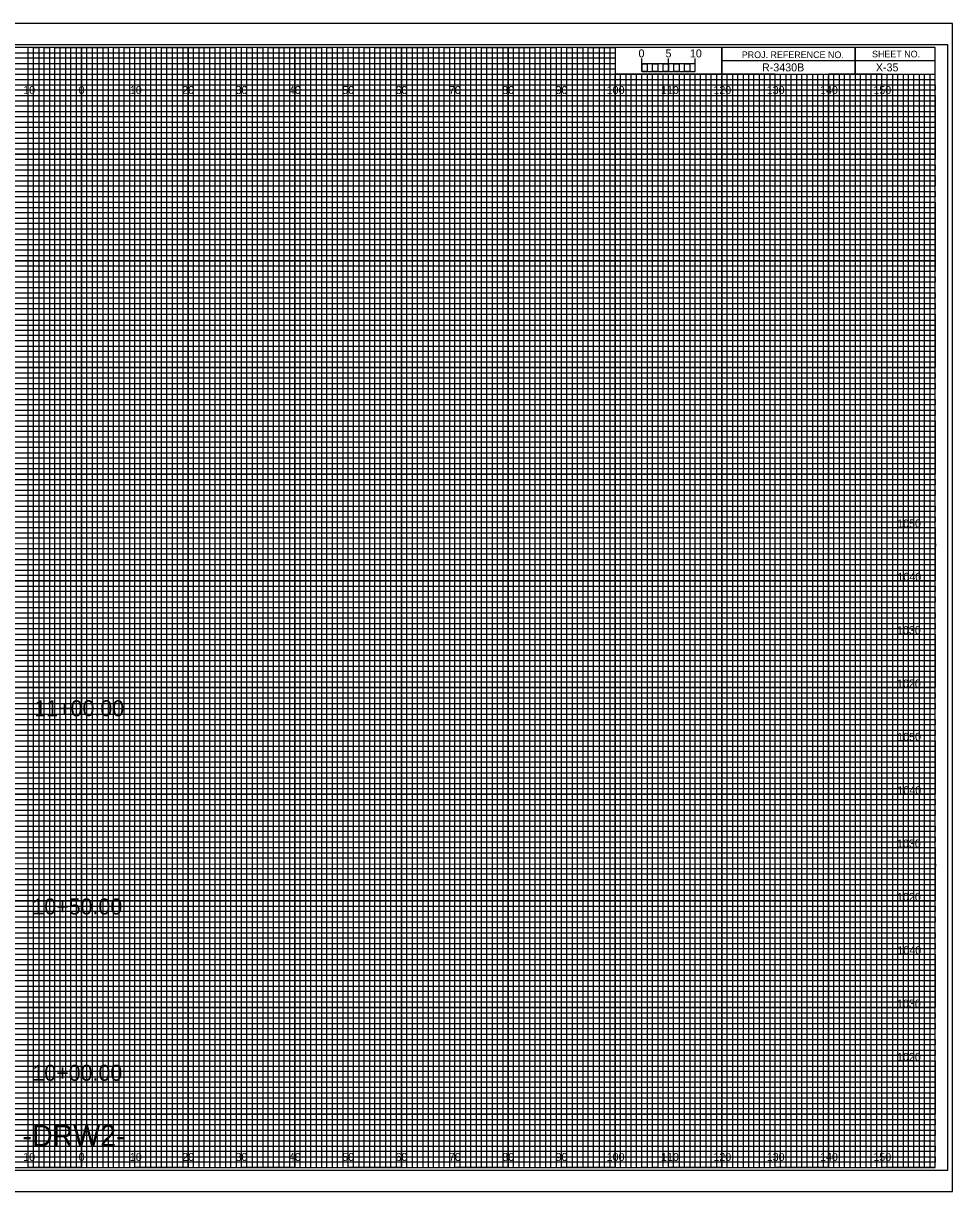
# Model space of a CAD drawing. Extents: x -13 to 323, y -5 to 215.
# Drawn here: x 149.1 to 323.3, y -4.5 to 214.5 of the extents above; entities that cross this region are included whole.
import ezdxf

# ---------------------------------------------------------------- set-up
doc = ezdxf.new("R2010")
doc.units = 0
for name, color, linetype in [('Prop XS Alignment Label', 7, 'Continuous'), ('Prop XS Bar Scale Labels', 7, 'Continuous'), ('Prop XS Elevation Labels', 7, 'Continuous'), ('Prop XS Offset Labels', 7, 'Continuous'), ('Prop XS Project Number', 7, 'Continuous'), ('Prop XS Sheet Number', 7, 'Continuous'), ('Prop XS Station Labels', 7, 'Continuous'), ('Sheet Cross Section CELL', 7, 'Continuous'), ('Sheet Cross Section Grid Major CELL', 7, 'Continuous'), ('Sheet Cross Section Grid Middle CELL', 7, 'Continuous'), ('Sheet Cross Section Grid Minor 1 CELL', 7, 'Continuous'), ('Sheet Cross Section Grid Minor 2 CELL', 7, 'Continuous'), ('Sheet Cross Section Scale CELL', 7, 'Continuous'), ('Sheet Cutting Line CELL', 7, 'Continuous'), ('Sheet DOT Grid CELL', 7, 'Continuous'), ('Sheet Plot Border Inside CELL', 7, 'Continuous'), ('Sheet Plot Border Outside CELL', 7, 'Continuous')]:
    doc.layers.add(name, color=color, linetype=linetype)

msp = doc.modelspace()

# ---------------------------------------------------------------- linework, layer by layer
at = {"layer": 'Sheet Cross Section CELL'}
for p, q in [((305, 210), (305, 205)), ((305, 205), (305, 210)), ((280, 207.5), (280, 205)), ((320, 207.49), (280, 207.49)), ((280, 205), (320, 205))]:
    msp.add_line(p, q, dxfattribs=at)
for points in [[(320, 210), (0, 210), (0, 0), (320, 0)], [(280, 210), (260, 210), (260, 205.03), (280, 205.03)], [(320, 210), (280, 210), (280, 205), (320, 205)]]:
    msp.add_lwpolyline(points, close=True, dxfattribs=at)
at = {"layer": 'Sheet Cross Section Grid Major CELL'}
for p, q in [((150, 210), (140, 210)), ((150, 0), (150, 210)), ((170, 210), (160, 210)), ((160, 210), (160, 0)), ((170, 0), (170, 210)), ((190, 210), (180, 210)), ((180, 210), (180, 0)), ((190, 0), (190, 210)), ((210, 210), (200, 210)), ((200, 210), (200, 0)), ((210, 0), (210, 210)), ((230, 210), (220, 210)), ((220, 210), (220, 0)), ((230, 0), (230, 210)), ((250, 210), (240, 210)), ((240, 210), (240, 0)), ((250, 0), (250, 210)), ((260, 210), (260, 0)), ((270, 0), (270, 205)), ((290, 205), (280, 205)), ((280, 205), (280, 0)), ((290, 0), (290, 205)), ((310, 205), (300, 205)), ((300, 205), (300, 0)), ((310, 0), (310, 205)), ((160, 0), (150, 0)), ((180, 0), (170, 0)), ((200, 0), (190, 0)), ((220, 0), (210, 0)), ((240, 0), (230, 0)), ((260, 0), (250, 0)), ((280, 0), (270, 0)), ((300, 0), (290, 0)), ((320, 0), (310, 0)), ((320, 0), (320, 0))]:
    msp.add_line(p, q, dxfattribs=at)
for points in [[(0, 200), (320, 200), (320, 190), (0, 190)], [(0, 180), (320, 180), (320, 170), (0, 170)], [(0, 160), (320, 160), (320, 150), (0, 150)], [(0, 140), (320, 140), (320, 130), (0, 130)], [(0, 120), (320, 120), (320, 110), (0, 110)], [(0, 100), (320, 100), (320, 90), (0, 90)], [(0, 80), (320, 80), (320, 70), (0, 70)], [(0, 60), (320, 60), (320, 50), (0, 50)], [(0, 40), (320, 40), (320, 30), (0, 30)], [(0, 20), (320, 20), (320, 10), (0, 10)]]:
    msp.add_lwpolyline(points, dxfattribs=at)
at = {"layer": 'Sheet Cross Section Grid Middle CELL'}
for points in [[(145, 0), (155, 0), (155, 210), (165, 210), (165, 0), (175, 0), (175, 210), (185, 210), (185, 0), (195, 0), (195, 210), (205, 210), (205, 0), (215, 0), (215, 210), (225, 210), (225, 0), (235, 0), (235, 210), (245, 210), (245, 0), (255, 0), (255, 210), (259.93, 210), (260, 210), (260, 205), (264.99, 205), (264.99, 0), (275, 0), (275, 205), (285, 205), (285, 0), (295, 0), (295, 205), (305, 205), (305, 0), (315, 0), (315, 205)], [(0, 205), (275, 205)], [(0, 185), (320, 185), (320, 195), (0, 195)], [(0, 165), (320, 165), (320, 175), (0, 175)], [(0, 145), (320, 145), (320, 155), (0, 155)], [(0, 125), (320, 125), (320, 135), (0, 135)], [(0, 105), (320, 105), (320, 115), (0, 115)], [(0, 85), (320, 85), (320, 95), (0, 95)], [(0, 65), (320, 65), (320, 75), (0, 75)], [(0, 45), (320, 45), (320, 55), (0, 55)], [(0, 25), (320, 25), (320, 35), (0, 35)], [(0, 5), (320, 5), (320, 15), (0, 15)]]:
    msp.add_lwpolyline(points, dxfattribs=at)
at = {"layer": 'Sheet Cross Section Grid Minor 1 CELL'}
for p, q in [((0, 209), (260, 209)), ((260, 209), (260, 207.98)), ((260, 207.98), (0, 207.98)), ((0, 207), (260, 207)), ((260, 205.89), (0, 205.89)), ((260, 207), (260, 205.89)), ((0, 204), (320, 204))]:
    msp.add_line(p, q, dxfattribs=at)
for points in [[(0, 203), (270, 203), (320, 203), (320, 202), (0, 202)], [(0, 201), (320, 201), (320, 199), (0, 199)], [(0, 198), (320, 198), (320, 197), (0, 196.98)], [(0, 196), (320, 196), (320, 194), (0, 194)], [(0, 193), (320, 193), (320, 192), (0, 192)], [(0, 191), (320, 191), (320, 189), (0, 189)], [(0, 188), (320, 188), (320, 187), (0, 187)], [(0, 186), (320, 186), (320, 184), (0, 184)], [(0, 183), (320, 183), (320, 182), (0, 182)], [(0, 181), (320, 181), (320, 179), (0, 179)], [(0, 178), (320, 178), (320, 177), (0, 177)], [(0, 176), (320, 176), (320, 173.95), (320, 173), (320, 172), (0, 172)], [(0, 174), (320, 174), (320, 173), (0, 173)], [(0, 171), (320, 171), (320, 169), (0, 169.03)], [(0, 169.03), (320, 169), (320, 168), (0, 168)], [(0, 167), (320, 167), (320, 166), (0, 166)], [(0, 164), (320, 164), (320, 163), (0, 163)], [(0, 162), (320, 162), (320, 161), (0, 161)], [(-0.07, 158.89), (320, 158.89), (320, 157.88), (-0.07, 157.88)], [(0, 157), (320, 157), (320, 156), (0, 156)], [(0, 154), (320, 154), (320, 153), (0, 153)], [(0, 152), (320, 152), (320, 151), (0, 151)], [(0, 149), (320, 149), (320, 148), (0, 148)], [(0, 147), (320, 147), (320, 146), (0, 146)], [(0, 144), (320, 144), (320, 143), (0, 143)], [(0, 142), (320, 142), (320, 141), (0, 141)], [(0, 139), (320, 139), (319.99, 137.98), (0, 138)], [(0, 137), (320, 137), (320, 136), (0, 136)], [(0, 134), (320, 134), (320, 133), (0, 133)], [(0, 132), (320, 132), (320, 131), (0, 131)], [(0, 129), (320, 129), (320, 128), (0, 128)], [(0, 127), (320, 127), (320, 126), (0, 126)], [(0, 124), (320, 124), (320, 123), (0, 123)], [(0, 122), (320, 122), (320, 121), (0, 121)], [(0, 119), (320, 119), (320, 118), (0, 118)], [(0, 116.99), (320.07, 116.91), (320, 116), (0, 116)], [(0, 114), (320, 114), (320, 113), (0, 113)], [(0, 112), (320, 112), (320, 111), (0, 111)], [(0, 109), (320, 109), (320, 108), (0, 108)], [(0, 107), (320, 107), (320, 106), (0, 106)], [(0, 104), (320, 104), (320, 103), (0, 103)], [(0, 102), (320, 102), (320, 101), (0, 101)], [(0, 99), (320, 99), (320, 98), (0, 98)], [(0, 97), (320, 97), (320, 96), (0, 96)], [(0, 94), (320, 94), (320, 93), (0, 93)], [(0, 92), (320, 92), (320, 91), (0, 91)], [(0, 89), (320, 89), (320, 88), (0, 88)], [(0, 87), (320, 87), (320, 86), (0, 86)], [(0, 84), (320, 84), (320, 83), (0, 83)], [(0, 82), (320, 82), (320, 81), (0, 81)], [(0, 79), (320, 79), (319.99, 77.98), (0, 78)], [(0, 77), (320, 77), (320, 76), (0, 76)], [(0, 74), (320, 74), (320, 73), (0, 73)], [(0, 72), (320, 72), (320, 71), (0, 71)], [(0, 69), (320, 69), (320, 68), (0, 68)], [(0, 67), (320, 67), (320, 66), (0, 66)], [(0, 64), (320, 64), (320, 63), (0, 63)], [(0, 62), (320, 62), (320, 61), (0, 61)], [(0, 59), (320, 59), (320, 58), (0, 58)], [(0, 56.99), (320.07, 56.91), (320, 56), (0, 56)], [(0, 54), (320, 54), (320, 53), (0, 53)], [(0, 52), (320, 52), (320, 51), (0, 51)], [(0, 49), (320, 49), (320, 48), (0, 48)], [(0, 47), (320, 47), (320, 46), (0, 46)], [(0, 44), (320, 44), (320, 43), (0, 43)], [(0, 42), (320, 42), (320, 41), (0, 41)], [(0, 39), (320, 39), (320, 38), (0, 38)], [(0, 37), (320, 37), (320, 36), (0, 36)], [(0, 34), (320, 34), (320, 33), (0, 33)], [(0, 32), (320, 32), (320, 31), (0, 31)], [(0, 29), (320, 29), (320, 28), (0, 28)], [(0, 27), (320, 27), (320, 26), (0, 26)], [(0, 24), (320, 24), (320, 23), (0, 23)], [(0, 22), (320, 22), (320, 21), (0, 21)], [(0, 19), (320, 19), (320, 18), (0, 18)], [(0, 17), (320, 17), (320, 16), (0, 16)], [(0, 14), (320, 14), (320, 13), (0, 13)], [(0, 12), (320, 12), (320, 11), (0, 11)], [(0, 9), (320, 9), (320, 8), (0, 8)], [(0, 7), (320, 7), (320, 6), (0, 6)], [(0, 4), (320, 4), (320, 3), (0, 3)], [(0, 2), (320, 2), (320, 1), (0, 1)]]:
    msp.add_lwpolyline(points, dxfattribs=at)
at = {"layer": 'Sheet Cross Section Grid Minor 2 CELL'}
for p, q in [((267, 205), (266.01, 205)), ((266.01, 205), (266.01, 0)), ((267, 0), (267, 205)), ((269, 205), (268, 205)), ((268, 205), (268, 0)), ((269, 0), (269, 205)), ((266.01, 0), (265, 0)), ((268, 0), (267, 0))]:
    msp.add_line(p, q, dxfattribs=at)
for points in [[(150, 0), (151, 0), (151, 210), (152, 210), (152, 0)], [(152, 0), (153, 0), (153, 210), (154, 210), (154, 0)], [(155, 0), (156, 0), (156, 210), (157, 210), (157, 0)], [(157, 0), (158, 0), (158, 210), (159, 210), (159, 0)], [(160, 0), (161, 0), (161, 210), (162, 210), (162, 0)], [(162, 0), (163, 0), (163, 210), (164, 210), (164, 0)], [(165, 0), (166, 0), (166, 210), (167, 210), (167, 0)], [(167, 0), (168, 0), (168, 210), (169, 210), (169, 0)], [(170, 0), (171, 0), (171, 210), (172, 210), (172, 0)], [(172, 0), (173, 0), (173, 210), (174, 210), (174, 0)], [(175, 0), (176, 0), (176, 210), (177, 210), (177, 0)], [(177, 0), (178, 0), (178, 210), (179, 210), (179, 0)], [(180, 0), (181, 0), (181, 210), (182, 210), (182, 0)], [(182, 0), (183, 0), (183, 210), (184, 210), (184, 0)], [(185, 0), (186, 0), (186, 210), (187, 210), (187, 0)], [(187, 0), (188, 0), (188, 210), (189, 210), (189, 0)], [(190, 0), (191, 0), (191, 210), (192, 210), (192, 0)], [(192, 0), (193, 0), (193, 210), (194, 210), (194, 0)], [(195, 0), (196, 0), (196, 210), (197, 210), (197, 0)], [(197, 0), (198, 0), (198, 210), (199, 210), (199, 0)], [(200, 0), (201, 0), (201, 210), (202, 210), (202, 0)], [(202, 0), (203, 0), (203, 210), (204, 210), (204, 0)], [(205, 0), (206, 0), (206, 210), (207, 210), (207, 0)], [(207, 0), (208, 0), (208, 210), (209, 210), (209, 0)], [(210, 0), (211, 0), (211, 210), (212, 210), (212, 0)], [(212, 0), (213, 0), (213, 210), (214, 210), (214, 0)], [(215, 0), (216, 0), (216, 210), (217, 210), (217, 0)], [(217, 0), (218, 0), (218, 210), (219, 210), (219, 0)], [(220, 0), (221, 0), (221, 210), (222, 210), (222, 0)], [(222, 0), (223, 0), (223, 210), (224, 210), (224, 0)], [(225, 0), (226, 0), (226, 210), (227, 210), (227, 0)], [(227, 0), (228, 0), (228, 210), (229, 210), (229, 0)], [(230, 0), (231, 0), (231, 210), (232, 210), (232, 0)], [(232, 0), (233, 0), (233, 210), (234, 210), (234, 0)], [(235, 0), (236, 0), (236, 210), (237, 210), (237, 0)], [(237, 0), (238, 0), (238, 210), (239, 210), (239, 0)], [(240, 0), (241, 0), (241, 210), (242, 210), (242, 0)], [(242, 0), (243, 0), (243, 210), (244, 210), (244, 0)], [(245, 0), (246, 0), (246, 210), (247, 210), (247, 0)], [(247, 0), (248, 0), (248, 210), (249, 210), (249, 0)], [(250, 0), (251, 0), (251, 210), (252, 210), (252, 0)], [(252, 0), (253, 0), (253, 210), (254, 210), (254, 0)], [(255, 0), (256, 0), (256, 210), (257, 210), (257, 0)], [(257, 0), (258, 0), (258, 210), (259, 210), (259, 0)], [(260, 0), (261, 0), (261, 205), (262.02, 205), (262.02, 0)], [(262, 0), (263, 0), (263, 205), (263.99, 205), (263.99, 0)], [(270, 0), (270.98, 0), (270.98, 205), (272, 205), (272, 0)], [(272, 0), (273, 0), (273, 205), (274.05, 205), (274.05, 0)], [(275, 0), (276, 0), (276, 205), (277, 205), (277, 0)], [(277, 0), (278, 0), (278, 205), (279, 205), (279, 0)], [(280, 0), (281, 0), (281, 205), (282, 205), (282, 0)], [(282, 0), (283, 0), (283, 205), (284, 205), (284, 0)], [(285, 0), (286, 0), (286, 205), (287, 205), (287, 0)], [(287, 0), (288, 0), (288, 205), (289, 205), (289, 0)], [(290, 0), (291, 0), (291, 205), (292, 205), (292, 0)], [(292, 0), (293, 0), (293, 205), (294, 205), (294, 0)], [(295, 0), (296, 0), (296, 205), (297, 205), (297, 0)], [(297, 0), (298, 0), (298, 205), (299, 205), (299, 0)], [(300, 0), (301, 0), (301, 205), (302, 205), (302, 0)], [(302, 0), (303, 0), (303, 205), (304, 205), (304, 0)], [(305, 0), (306, 0), (306, 205), (307, 205), (307, 0)], [(307, 0), (308, 0), (308, 205), (309, 205), (309, 0)], [(310, 0), (311, 0), (311, 205), (312, 205), (312, 0)], [(312, 0), (313, 0), (313, 205), (314, 205), (314, 0)], [(315, 0), (316, 0), (316, 205), (317, 205), (317, 0)], [(317, 0), (318, 0), (318, 205), (319, 205), (319, 0)]]:
    msp.add_lwpolyline(points, dxfattribs=at)
at = {"layer": 'Sheet Cross Section Scale CELL'}
for p, q in [((265, 205.49), (265, 207.9)), ((265, 206.9), (265, 207.9)), ((270, 205.49), (270, 207.9)), ((275, 205.49), (275, 207.9)), ((275, 206.9), (275, 207.9))]:
    msp.add_line(p, q, dxfattribs=at)
for points in [[(275, 206.9), (265, 206.9), (265, 205.49), (275, 205.49)], [(265, 206.9), (266, 206.9), (266, 205.49), (265, 205.49)], [(267, 206.9), (268, 206.9), (268, 205.49), (267, 205.49)], [(269, 206.9), (270, 206.9), (270, 205.49), (269, 205.49)], [(271, 206.9), (272, 206.9), (272, 205.49), (271, 205.49)], [(273, 206.9), (274, 206.9), (274, 205.49), (273, 205.49)]]:
    msp.add_lwpolyline(points, close=True, dxfattribs=at)
at = {"layer": 'Sheet Cutting Line CELL'}
for p, q in [((323.3, 214.5), (-13.4, 214.5)), ((-13.4, -4.5), (323.3, -4.5))]:
    msp.add_line(p, q, dxfattribs=at)
at = {"layer": 'Sheet DOT Grid CELL'}
for p, q in [((150, 0), (150, 210)), ((160, 0), (160, 210)), ((170, 0), (170, 210)), ((180, 0), (180, 210)), ((190, 0), (190, 210)), ((200, 0), (200, 210)), ((210, 0), (210, 210)), ((220, 0), (220, 210)), ((230, 0), (230, 210)), ((240, 0), (240, 210)), ((250, 0), (250, 210)), ((260, 0), (260, 204.69)), ((270, 0), (270, 204.69)), ((280, 0), (280, 204.69)), ((290, 0), (290, 204.69)), ((300, 0), (300, 204.69)), ((310, 0), (310, 204.69)), ((0, 200), (320, 200)), ((0, 190), (320, 190)), ((0, 180), (320, 180)), ((0, 170), (320, 170)), ((0, 160), (320, 160)), ((0, 150), (320, 150)), ((0, 140), (320, 140)), ((0, 130), (320, 130)), ((0, 120), (320, 120)), ((0, 110), (320, 110)), ((0, 100), (320, 100)), ((0, 90), (320, 90)), ((0, 80), (320, 80)), ((0, 70), (320, 70)), ((0, 60), (320, 60)), ((0, 50), (320, 50)), ((0, 40), (320, 40)), ((0, 30), (320, 30)), ((0, 20), (320, 20)), ((0, 10), (320, 10))]:
    msp.add_line(p, q, dxfattribs=at)
at = {"layer": 'Sheet Plot Border Inside CELL'}
msp.add_lwpolyline([(-10.8, -0.5), (322.4, -0.5), (322.4, 210.5), (-10.8, 210.5)], close=True, dxfattribs=at)
at = {"layer": 'Sheet Plot Border Outside CELL'}
msp.add_lwpolyline([(-13.4, -4.5), (323.3, -4.5), (323.3, 214.5), (-13.4, 214.5)], close=True, dxfattribs=at)

# ---------------------------------------------------------------- texts
at = {"layer": 'Prop XS Alignment Label'}
msp.add_text('-DRW2-', height=4, dxfattribs=at).set_placement((148.92, 4))
at = {"layer": 'Prop XS Bar Scale Labels'}
for s, p in [('5', (269.47, 208.12)), ('10', (274.04, 208.12))]:
    msp.add_text(s, height=1.5, dxfattribs=at).set_placement(p)
at = {"layer": 'Prop XS Elevation Labels'}
for s, p in [('1050', (312.9, 120)), ('1040', (312.95, 110)), ('1030', (312.86, 100)), ('1020', (312.87, 90)), ('1050', (312.9, 80)), ('1040', (312.95, 70)), ('1030', (312.86, 60)), ('1020', (312.87, 50)), ('1040', (312.95, 40)), ('1030', (312.86, 30)), ('1020', (312.87, 20))]:
    msp.add_text(s, height=1.5, dxfattribs=at).set_placement(p)
at = {"layer": 'Prop XS Offset Labels'}
for s, p in [('10', (149.04, 201.25)), ('0', (159.45, 201.25)), ('0', (159.45, 201.25)), ('10', (169.04, 201.25)), ('20', (178.86, 201.25)), ('30', (188.86, 201.25)), ('40', (198.86, 201.25)), ('50', (208.86, 201.25)), ('60', (218.86, 201.25)), ('70', (228.86, 201.25)), ('80', (238.86, 201.25)), ('90', (248.86, 201.25)), ('100', (258.44, 201.25)), ('110', (268.62, 201.25)), ('120', (278.44, 201.25)), ('130', (288.44, 201.25)), ('140', (298.44, 201.25)), ('150', (308.44, 201.25)), ('10', (149.04, 1.25)), ('0', (159.45, 1.25)), ('0', (159.45, 1.25)), ('10', (169.04, 1.25)), ('20', (178.86, 1.25)), ('30', (188.86, 1.25)), ('40', (198.86, 1.25)), ('50', (208.86, 1.25)), ('60', (218.86, 1.25)), ('70', (228.86, 1.25)), ('80', (238.86, 1.25)), ('90', (248.86, 1.25)), ('100', (258.44, 1.25)), ('110', (268.62, 1.25)), ('120', (278.44, 1.25)), ('130', (288.44, 1.25)), ('140', (298.44, 1.25)), ('150', (308.44, 1.25))]:
    msp.add_text(s, height=1.5, dxfattribs=at).set_placement(p)
at = {"layer": 'Prop XS Project Number'}
msp.add_text('R-3430B', height=1.5, dxfattribs=at).set_placement((287.56, 205.5))
at = {"layer": 'Prop XS Sheet Number'}
msp.add_text('X-35', height=1.5, dxfattribs=at).set_placement((308.9, 205.5))
at = {"layer": 'Prop XS Station Labels'}
for s, p in [('11+00.00', (151.13, 84.61)), ('10+50.00', (150.77, 47.46)), ('10+00.00', (150.77, 16.28))]:
    msp.add_text(s, height=3, dxfattribs=at).set_placement(p)
at = {"layer": 'Sheet Cross Section CELL'}
for s, p in [('PROJ. REFERENCE NO.', (283.77, 207.99)), ('SHEET NO.', (308.19, 208.12))]:
    msp.add_text(s, height=1.25, dxfattribs=at).set_placement(p)
at = {"layer": 'Sheet Cross Section Scale CELL'}
msp.add_text('0', height=1.5, dxfattribs=at).set_placement((264.41, 208.12))

doc.saveas('drawing.dxf')
